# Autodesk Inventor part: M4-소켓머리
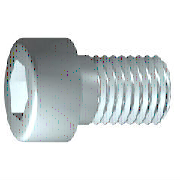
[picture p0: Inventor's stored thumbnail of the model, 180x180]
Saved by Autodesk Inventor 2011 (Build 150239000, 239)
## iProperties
IsCustomPart: 0
Created: 2009-02
Part Number: M4-소켓머리
Material: 강, 연강
Description: 6각머리 태핑 나사
Document SubType Name: Modeling
Standard: KS B 1003
Designer: 한국산업디자인학원 [http://gmhk.co.kr]
Standards Organization: KS
Language: ko-KR
Size Designation: M 4 x 12
Categories: <MemberInstance><Categories><Category DisplayName="조임쇠" InternalName="e4da775c-781d-43d5-af7c-5136215cf5a6" Mnemonic="FSTN"><Category DisplayName="볼트" InternalN
Density: 7.86 g/cm^3
Mass: 2.23465 g
Surface Area: 3.30853 cm^2
Volume: 0.284306 cm^3
Author: pww
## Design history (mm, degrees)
revolve "본체" stored, may be unused: angle "d10" = 90 deg
sketch "스케치2"
  geometry: L1 (0, -4.9)-(0, 4.9) reference; L2 (-4.9, 0)-(4.9, 0) reference; L3 (1.732, 0)-(0.866, -1.5); L4 (0.866, -1.5)-(-0.866, -1.5); L5 (-0.866, -1.5)-(-1.732, 0); L6 (-1.732, 0)-(-0.866, 1.5); L7 (-0.866, 1.5)-(0.866, 1.5); L8 (0.866, 1.5)-(1.732, 0); 2 further points
  constraints: 12 end point, 1 coincident, 1 horizontal alignment, 1 point on line, 12 other
extrude "슬롯" join sketch "스케치2" stored distance "d11" = 10; taper "d12" = 0 deg
workplane "Work Plane1"
fillet "Fillet2" dims "d30" = 0.1 (= R)
body "Solid1"
fillet "모깎기1" dims "d17" = 0.4 (= RR)
feature "스레드" dims "d13" = 10.25 (= GEL), "d14" = 0
chamfer "모따기1" distance "d15" = 0.42941 (= -0.5 x SPD + 0.5 x GD); stored, may be unused: second distance "d16" = 0.42941 (= GUL), angle "d27" = 45 deg
sketch "스케치1"
  geometry: L1 (-1, 0)-(12, 0); L2 (12, 0)-(12, 2); L3 (12, 2)-(1.75, 2); L4 (1.75, 2)-(1.32, 2); L5 (1.32, 2)-(0, 2); L6 (0, 2)-(0, 3.5); L7 (0, 3.5)-(-4, 3.5); L8 (-4, 3.5)-(-4, 1.732); L9 (-4, 1.732)-(-2, 1.732); L10 (-2, 1.732)-(-1, 0); L11 (-7.2, 0)-(15.2, 0) reference; L12 (0, -0.7)-(0, 4.2) reference; L13 (1.75, 2)-(0, 2)
  constraints: 22 end point, 6 parallel, 2 collinear, 2 perpendicular, 1 horizontal, 1 point on line
  dimensions: "d1" = 10.25 distance from line of L3.end L2 (= GEL); "d2" = 0.42952 distance of L4.end L3.end (computed from GAL); "d3" = 4 distance between parallel lines of L8 L6 (= KOH); "d4" = 2 distance of L8.end L9.end (= INTI); "d5" = 60 deg angle of L10 L1; "d6" = 4 diameter of L3 L1 (= GD); "d7" = 4 diameter of L5 L1 (= BDM); "d8" = 3.4641 diameter of L9 L1 (= 1.1547 x SW); "d9" = 7 diameter of L7 L1 (= KOD); "d26" = 12 distance between parallel lines of L12 L2 (= NLG)
other parameters: "GD" = 4 (= NND) [user parameter; used in 2 equation terms], "NLG" = 12 [user parameter; used in 1 equation term], "GEL" = 10.25 [user parameter; used in 2 equation terms], "KOD" = 7 [user parameter; used in 1 equation term], "KOH" = 4 [user parameter; used in 1 equation term], "INTI" = 2 [user parameter; used in 1 equation term], "GAL" = 0.42941 (= 0.61345 x PTC) [user parameter; used in 1 equation term], "GUL" = 0.42941 (= 0.61345 x PTC) [user parameter; used in 1 equation term], "BDM" = 4 (= NND) [user parameter; used in 1 equation term], "SW" = 3 [user parameter; used in 2 equation terms], "RR" = 0.4 [user parameter; used in 1 equation term], "SPD" = 3.14117 (= NND - 1.2269 x PTC) [user parameter; used in 1 equation term], "d19" = 0, "d28" = 0, "d29" = 0, "R" = 0.1 [user parameter; used in 1 equation term], "PHH" = 0.2 [user parameter], "GD1" = 3.14117 (= THREADDIA - 1.2269 x PTC) [user parameter], "THREADDIA" = 4 [user parameter; used in 1 equation term], "FAWI" = 45 deg [user parameter], "TPU" = 14.28571 (computed from PTC) [user parameter], "PTC" = 0.7 [user parameter; used in 5 equation terms], "NND" = 4 [user parameter; used in 3 equation terms], "TOA" = 30 deg [user parameter], "E0" = 3.465 (= 1.155 x SW) [user parameter]
